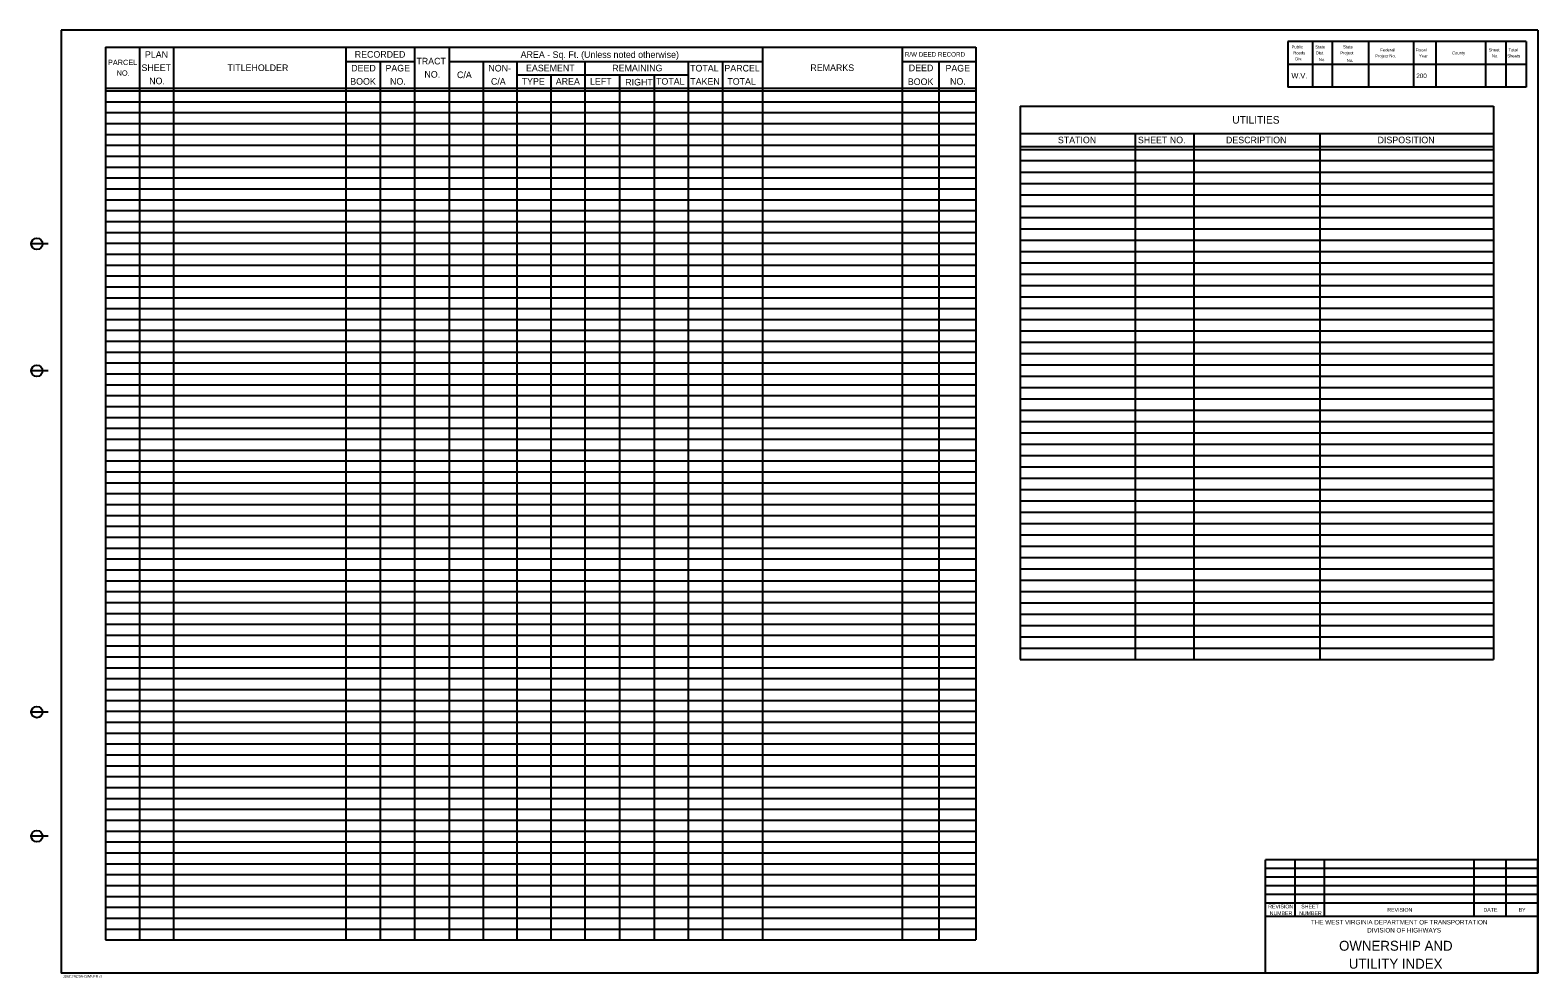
# Model space of a CAD drawing. Extents: x -16.4 to 16.9, y -10.4 to 10.5.
import ezdxf

# ---------------------------------------------------------------- set-up
doc = ezdxf.new("R2010")
doc.units = 0
doc.layers.add('BORDERS SHEET', color=7, linetype='Continuous')

msp = doc.modelspace()

# ---------------------------------------------------------------- linework, layer by layer
at = {"layer": 'BORDERS SHEET'}
for p, q in [((-15.68, 10.459), (-15.68, -10.337)), ((16.872, 10.459), (-15.68, 10.459)), ((-15.68, 10.459), (-15.68, 10.459)), ((16.872, 10.459), (16.872, -10.337)), ((16.872, 10.459), (16.872, 10.459)), ((-14.699, 10.08), (-14.699, -9.6)), ((-14.699, 10.08), (4.483, 10.08)), ((-13.951, 10.08), (-13.951, -9.6)), ((-13.201, 10.08), (-13.201, -9.6)), ((-9.406, 10.08), (-9.406, -9.6)), ((-7.889, 10.08), (-7.889, -9.6)), ((-7.128, 10.08), (-7.128, -9.6)), ((-0.217, 10.08), (-0.217, -9.6)), ((2.857, 10.08), (2.857, -9.6)), ((4.483, 10.08), (4.483, -9.6)), ((16.615, 10.209), (11.365, 10.209)), ((11.365, 10.209), (11.365, 9.202)), ((11.907, 10.209), (11.907, 9.202)), ((12.341, 10.209), (12.341, 9.202)), ((13.136, 10.209), (13.136, 9.202)), ((14.128, 10.207), (14.128, 9.201)), ((14.624, 10.207), (14.624, 9.201)), ((15.715, 10.209), (15.715, 9.202)), ((16.165, 10.209), (16.165, 9.202)), ((16.615, 10.209), (16.615, 9.202)), ((-9.406, 9.768), (-7.889, 9.768)), ((-8.644, 9.77), (-8.644, -9.6)), ((-7.128, 9.768), (-0.217, 9.768)), ((-6.378, 9.768), (-6.378, -9.6)), ((-5.632, 9.768), (-5.632, -9.6)), ((-4.133, 9.768), (-4.133, -9.6)), ((-1.858, 9.768), (-1.858, -9.6)), ((-1.1, 9.768), (-1.1, -9.6)), ((2.857, 9.768), (4.487, 9.768)), ((3.672, 9.768), (3.672, -9.6)), ((16.615, 9.704), (11.365, 9.704)), ((-5.632, 9.477), (-1.858, 9.477)), ((-4.883, 9.477), (-4.883, -9.6)), ((-3.368, 9.477), (-3.368, -9.6)), ((-2.603, 9.477), (-2.603, -9.6)), ((-14.699, 9.18), (4.483, 9.18)), ((-14.699, 9.12), (4.483, 9.12)), ((16.615, 9.202), (11.365, 9.202)), ((-14.699, 8.88), (4.483, 8.88)), ((5.463, 8.781), (5.463, -3.42)), ((5.463, 8.781), (15.892, 8.781)), ((15.892, 8.781), (15.892, -3.42)), ((-14.699, 8.64), (4.483, 8.64)), ((-14.699, 8.4), (4.483, 8.4)), ((-14.699, 8.16), (4.483, 8.16)), ((5.463, 8.181), (15.892, 8.181)), ((7.997, 8.181), (7.997, -3.42)), ((9.292, 8.181), (9.292, -3.42)), ((12.069, 8.181), (12.069, -3.42)), ((-14.699, 7.92), (4.483, 7.92)), ((-14.699, 7.68), (4.483, 7.68)), ((5.463, 7.892), (15.892, 7.892)), ((5.463, 7.83), (15.892, 7.83)), ((-14.699, 7.44), (4.483, 7.44)), ((5.463, 7.581), (15.892, 7.581)), ((5.463, 7.33), (15.892, 7.33)), ((-14.699, 7.2), (4.483, 7.2)), ((5.463, 7.08), (15.892, 7.08)), ((-14.699, 6.96), (4.483, 6.96)), ((-14.699, 6.72), (4.483, 6.72)), ((5.463, 6.831), (15.892, 6.831)), ((-14.699, 6.48), (4.483, 6.48)), ((5.463, 6.58), (15.892, 6.58)), ((5.463, 6.33), (15.892, 6.33)), ((-14.699, 6.24), (4.483, 6.24)), ((-14.699, 6), (4.483, 6)), ((5.463, 6.081), (15.892, 6.081)), ((-15.961, 5.748), (-16.361, 5.748)), ((-14.699, 5.76), (4.483, 5.76)), ((5.463, 5.83), (15.892, 5.83)), ((-14.699, 5.52), (4.483, 5.52)), ((5.463, 5.58), (15.892, 5.58)), ((5.463, 5.331), (15.892, 5.331)), ((-14.699, 5.28), (4.483, 5.28)), ((-14.699, 5.04), (4.483, 5.04)), ((5.463, 5.08), (15.892, 5.08)), ((-14.699, 4.8), (4.483, 4.8)), ((5.463, 4.83), (15.892, 4.83)), ((-14.699, 4.56), (4.483, 4.56)), ((5.463, 4.581), (15.892, 4.581)), ((5.463, 4.33), (15.892, 4.33)), ((-14.699, 4.32), (4.483, 4.32)), ((-14.699, 4.08), (4.483, 4.08)), ((5.463, 4.08), (15.892, 4.08)), ((-14.699, 3.84), (4.483, 3.84)), ((5.463, 3.831), (15.892, 3.831)), ((-14.699, 3.6), (4.483, 3.6)), ((-14.699, 3.36), (4.483, 3.36)), ((5.463, 3.58), (15.892, 3.58)), ((5.463, 3.33), (15.892, 3.33)), ((-14.699, 3.12), (4.483, 3.12)), ((5.463, 3.081), (15.892, 3.081)), ((-15.961, 2.948), (-16.361, 2.948)), ((-14.699, 2.88), (4.483, 2.88)), ((5.463, 2.83), (15.892, 2.83)), ((-14.699, 2.64), (4.483, 2.64)), ((-14.699, 2.4), (4.483, 2.4)), ((5.463, 2.58), (15.892, 2.58)), ((5.463, 2.331), (15.892, 2.331)), ((-14.699, 2.16), (4.483, 2.16)), ((5.463, 2.08), (15.892, 2.08)), ((-14.699, 1.92), (4.483, 1.92)), ((-14.699, 1.68), (4.483, 1.68)), ((5.463, 1.83), (15.892, 1.83)), ((-14.699, 1.44), (4.483, 1.44)), ((5.463, 1.581), (15.892, 1.581)), ((5.463, 1.33), (15.892, 1.33)), ((-14.699, 1.2), (4.483, 1.2)), ((5.463, 1.08), (15.892, 1.08)), ((-14.699, 0.96), (4.483, 0.96)), ((-14.699, 0.72), (4.483, 0.72)), ((5.463, 0.831), (15.892, 0.831)), ((-14.699, 0.48), (4.483, 0.48)), ((5.463, 0.58), (15.892, 0.58)), ((-14.699, 0.24), (4.483, 0.24)), ((-14.699, 0), (4.483, 0)), ((5.463, 0.33), (15.892, 0.33)), ((5.463, 0.081), (15.892, 0.081)), ((-14.699, -0.24), (4.483, -0.24)), ((5.463, -0.17), (15.892, -0.17)), ((-14.699, -0.48), (4.483, -0.48)), ((5.463, -0.42), (15.892, -0.42)), ((-14.699, -0.72), (4.483, -0.72)), ((-14.699, -0.96), (4.483, -0.96)), ((5.463, -0.669), (15.892, -0.669)), ((5.463, -0.92), (15.892, -0.92)), ((-14.699, -1.2), (4.483, -1.2)), ((5.463, -1.17), (15.892, -1.17)), ((-14.699, -1.44), (4.483, -1.44)), ((5.463, -1.419), (15.892, -1.419)), ((-14.699, -1.68), (4.483, -1.68)), ((-14.699, -1.92), (4.483, -1.92)), ((5.463, -1.67), (15.892, -1.67)), ((5.463, -1.92), (15.892, -1.92)), ((-14.699, -2.16), (4.483, -2.16)), ((5.463, -2.169), (15.892, -2.169)), ((-14.699, -2.4), (4.483, -2.4)), ((-14.699, -2.64), (4.483, -2.64)), ((5.463, -2.42), (15.892, -2.42)), ((-14.699, -2.88), (4.483, -2.88)), ((5.463, -2.67), (15.892, -2.67)), ((5.463, -2.919), (15.892, -2.919)), ((-14.699, -3.12), (4.483, -3.12)), ((5.463, -3.17), (15.892, -3.17)), ((-14.699, -3.36), (4.483, -3.36)), ((-14.699, -3.6), (4.483, -3.6)), ((5.463, -3.42), (15.892, -3.42)), ((-14.699, -3.84), (4.483, -3.84)), ((-14.699, -4.08), (4.483, -4.08)), ((-14.699, -4.32), (4.483, -4.32)), ((-15.961, -4.577), (-16.361, -4.577)), ((-14.699, -4.56), (4.483, -4.56)), ((-14.699, -4.8), (4.483, -4.8)), ((-14.699, -5.04), (4.483, -5.04)), ((-14.699, -5.28), (4.483, -5.28)), ((-14.699, -5.52), (4.483, -5.52)), ((-14.699, -5.76), (4.483, -5.76)), ((-14.699, -6), (4.483, -6)), ((-14.699, -6.24), (4.483, -6.24)), ((-14.699, -6.48), (4.483, -6.48)), ((-14.699, -6.72), (4.483, -6.72)), ((-14.699, -6.96), (4.483, -6.96)), ((-14.699, -7.2), (4.483, -7.2)), ((-15.961, -7.314), (-16.361, -7.314)), ((-14.699, -7.44), (4.483, -7.44)), ((-14.699, -7.68), (4.483, -7.68)), ((-14.699, -7.92), (4.483, -7.92)), ((10.872, -10.337), (10.872, -7.837)), ((16.872, -7.837), (10.872, -7.837)), ((11.522, -9.087), (11.522, -7.837)), ((12.173, -9.087), (12.173, -7.837)), ((15.472, -9.087), (15.472, -7.837)), ((16.172, -9.087), (16.172, -7.837)), ((16.872, -10.337), (16.872, -7.837)), ((-14.699, -8.16), (4.483, -8.16)), ((16.872, -8.027), (10.872, -8.027)), ((16.872, -8.217), (10.872, -8.217)), ((-14.699, -8.4), (4.483, -8.4)), ((-14.699, -8.64), (4.483, -8.64)), ((16.872, -8.407), (10.872, -8.407)), ((16.872, -8.597), (10.872, -8.597)), ((-14.699, -8.88), (4.483, -8.88)), ((16.872, -8.787), (10.872, -8.787)), ((-14.699, -9.12), (4.483, -9.12)), ((16.872, -9.087), (10.872, -9.087)), ((-14.699, -9.36), (4.483, -9.36)), ((-14.699, -9.6), (4.483, -9.6)), ((16.872, -10.337), (-15.68, -10.337)), ((-15.68, -10.337), (-15.68, -10.337)), ((16.872, -10.337), (10.872, -10.337)), ((16.872, -10.337), (16.872, -10.337))]:
    msp.add_line(p, q, dxfattribs=at)
for centre in [(-16.211, 5.748), (-16.211, 2.948), (-16.211, -4.577), (-16.211, -7.314)]:
    msp.add_circle(centre, 0.125, dxfattribs=at)

# ---------------------------------------------------------------- texts
for s, height, p in [('PLAN', 0.1458, (-13.831, 9.849)), ('RECORDED', 0.1458, (-9.206, 9.851)), ('AREA - Sq. Ft. (Unless noted otherwise)', 0.1458, (-5.549, 9.847)), ('R/W DEED RECORD', 0.1, (2.919, 9.874)), ('Public', 0.0666, (11.445, 10.057)), ('Roads', 0.0666, (11.479, 9.924)), ('State', 0.0666, (11.966, 10.057)), ('Dist.', 0.0666, (11.979, 9.924)), ('Project', 0.0666, (12.519, 9.924)), ('State', 0.0666, (12.58, 10.057)), ('Federal', 0.0666, (13.4, 9.99)), ('Fiscal', 0.0666, (14.178, 9.989)), ('County', 0.0666, (14.979, 9.923)), ('Sheet', 0.0666, (15.788, 9.99)), ('Total', 0.0666, (16.225, 9.99)), ('PARCEL', 0.1167, (-14.645, 9.689)), ('SHEET', 0.1458, (-13.907, 9.557)), ('TITLEHOLDER', 0.1458, (-12.013, 9.557)), ('DEED', 0.1458, (-9.284, 9.548)), ('PAGE', 0.1458, (-8.529, 9.548)), ('TRACT', 0.1458, (-7.847, 9.703)), ('NON-', 0.1458, (-6.261, 9.547)), ('EASEMENT', 0.1458, (-5.431, 9.55)), ('REMAINING', 0.1458, (-3.53, 9.55)), ('TOTAL', 0.1458, (-1.814, 9.547)), ('PARCEL', 0.1458, (-1.058, 9.547)), ('REMARKS', 0.1458, (0.838, 9.557)), ('DEED', 0.1458, (3.006, 9.553)), ('PAGE', 0.1458, (3.815, 9.547)), ('Div.', 0.0666, (11.525, 9.794)), ('No.', 0.0666, (12.046, 9.775)), ('No.', 0.0666, (12.66, 9.759)), ('Project No.', 0.0666, (13.289, 9.856)), ('Year', 0.0666, (14.254, 9.856)), ('No.', 0.0666, (15.862, 9.857)), ('Sheets', 0.0666, (16.2, 9.859)), ('NO.', 0.1167, (-14.454, 9.455)), ('NO.', 0.1458, (-13.737, 9.266)), ('BOOK', 0.1458, (-9.305, 9.256)), ('NO.', 0.1458, (-8.428, 9.256)), ('NO.', 0.1458, (-7.67, 9.411)), ('C/A', 0.1458, (-6.952, 9.401)), ('C/A', 0.1458, (-6.204, 9.255)), ('TYPE', 0.1458, (-5.527, 9.256)), ('AREA', 0.1458, (-4.775, 9.256)), ('LEFT', 0.1458, (-4.02, 9.256)), ('RIGHT', 0.1458, (-3.243, 9.239)), ('TOTAL', 0.1458, (-2.565, 9.256)), ('TAKEN', 0.1458, (-1.81, 9.255)), ('TOTAL', 0.1458, (-0.993, 9.255)), ('BOOK', 0.1458, (2.985, 9.249)), ('NO.', 0.1458, (3.916, 9.255)), ('W.V.', 0.1167, (11.441, 9.395)), ('200 ', 0.1, (14.194, 9.402)), ('UTILITIES', 0.1666, (10.138, 8.398)), ('STATION', 0.1458, (6.292, 7.964)), ('SHEET NO.', 0.1458, (8.056, 7.964)), ('DESCRIPTION', 0.1458, (9.998, 7.964)), ('DISPOSITION', 0.1458, (13.34, 7.964)), ('REVISION', 0.0833, (10.929, -8.904)), ('NUMBER', 0.0833, (10.961, -9.054)), ('NUMBER', 0.0833, (11.611, -9.054)), ('SHEET', 0.0833, (11.658, -8.904)), ('REVISION', 0.0833, (13.555, -8.979)), ('DATE', 0.0833, (15.674, -8.979)), ('BY', 0.0833, (16.449, -8.979)), ('THE WEST VIRGINIA DEPARTMENT OF TRANSPORTATION', 0.1, (11.871, -9.26)), ('    OWNERSHIP AND    ', 0.2187, (12.166, -9.839)), ('DIVISION OF HIGHWAYS', 0.1, (13.112, -9.437)), ('    UTILITY INDEX    ', 0.2187, (12.381, -10.234)), ('J06C29C98-OWNER d', 0.06, (-15.64, -10.436))]:
    msp.add_text(s, height=height, dxfattribs=at).set_placement(p)

doc.saveas('drawing.dxf')
